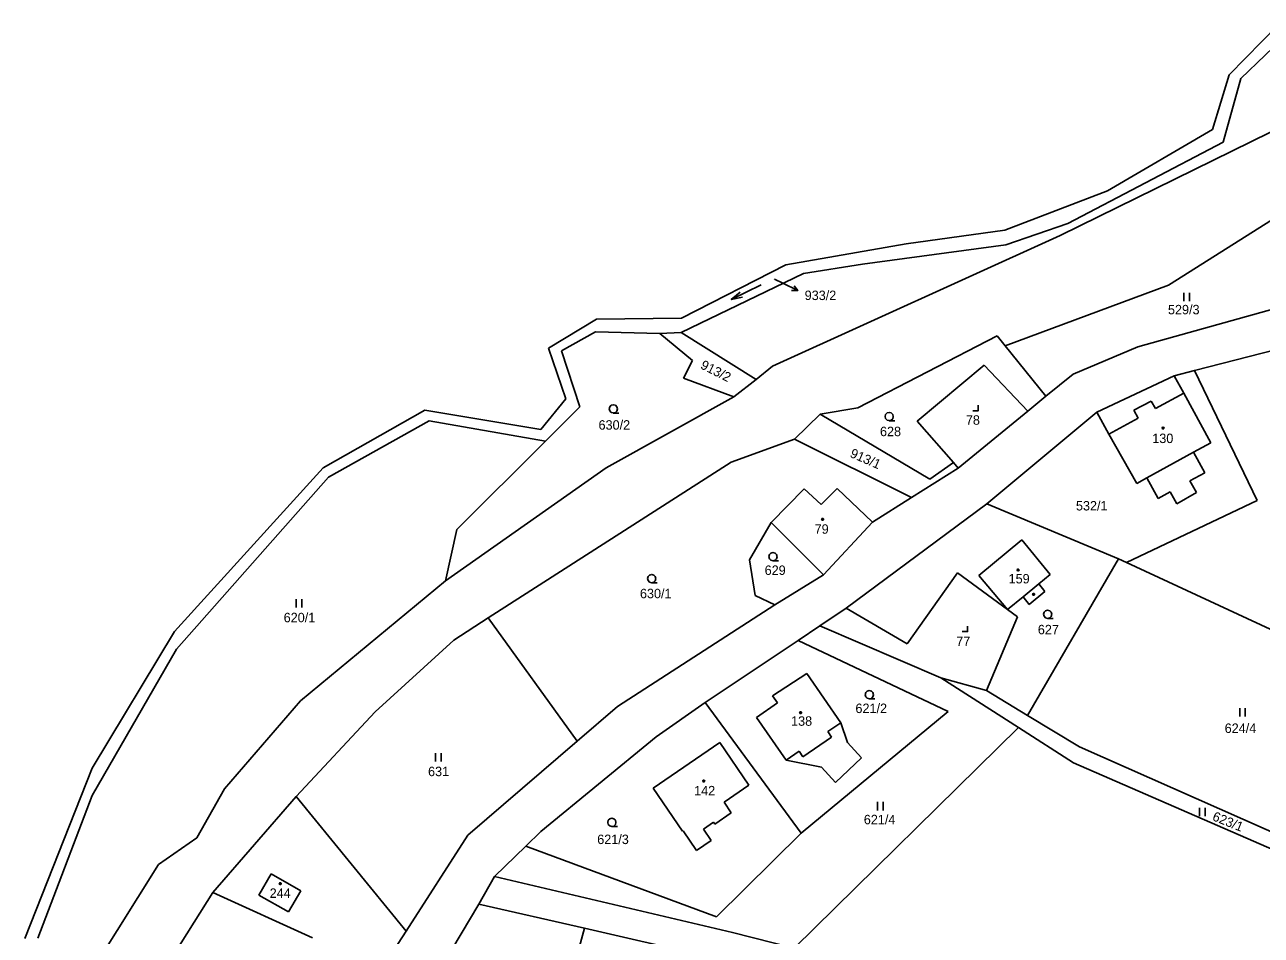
# Model space of a CAD drawing. Extents: x -580551 to -575069, y -1073031 to -1067931.
# Drawn here: x -578306.8 to -578084.3, y -1070524.1 to -1070360.2 of the extents above; entities that cross this region are included whole.
import ezdxf

# ---------------------------------------------------------------- set-up
doc = ezdxf.new("R2010")
doc.units = 0
for name, color, linetype in [('Druh pozemku', 7, 'Continuous'), ('Katastrální hranice', 7, 'Continuous'), ('Parcela', 7, 'Continuous'), ('Parcelní číslo', 7, 'Continuous'), ('Parcelní číslo_stavba', 7, 'Continuous'), ('Pomocná vrstva', 7, 'Continuous'), ('SR - hranice státu', 7, 'Continuous'), ('Vnitřní kresba', 7, 'Continuous')]:
    doc.layers.add(name, color=color, linetype=linetype)

msp = doc.modelspace()

# ---------------------------------------------------------------- linework, layer by layer
at = {"layer": 'Druh pozemku'}
for p, q in [((-578174.272, -1070407.069), (-578179.668, -1070409.691)), ((-578098.19, -1070408.5), (-578098.19, -1070410)), ((-578097.19, -1070410), (-578097.19, -1070408.5)), ((-578257.97, -1070463.65), (-578257.97, -1070465.15)), ((-578256.97, -1070465.15), (-578256.97, -1070463.65)), ((-578088.15, -1070483.24), (-578088.15, -1070484.74)), ((-578087.15, -1070484.74), (-578087.15, -1070483.24)), ((-578232.9, -1070491.36), (-578232.9, -1070492.86)), ((-578231.9, -1070492.86), (-578231.9, -1070491.36)), ((-578153.33, -1070500.13), (-578153.33, -1070501.63)), ((-578152.33, -1070501.63), (-578152.33, -1070500.13)), ((-578095.39, -1070501.16), (-578095.39, -1070502.66)), ((-578094.39, -1070502.66), (-578094.39, -1070501.16))]:
    msp.add_line(p, q, dxfattribs=at)
for points in [[(-578177.651, -1070409.267), (-578179.668, -1070409.691), (-578178.088, -1070408.367)], [(-578200.89, -1070430.11), (-578201.27, -1070430.01), (-578201.54, -1070429.74), (-578201.64, -1070429.37), (-578201.54, -1070429), (-578201.27, -1070428.73), (-578200.9, -1070428.63), (-578200.53, -1070428.73), (-578200.26, -1070429), (-578200.16, -1070429.38), (-578200.26, -1070429.76), (-578200.53, -1070430.03), (-578200.91, -1070430.13), (-578199.91, -1070430.13)], [(-578151.24, -1070431.49), (-578151.62, -1070431.39), (-578151.89, -1070431.12), (-578151.99, -1070430.75), (-578151.89, -1070430.38), (-578151.62, -1070430.11), (-578151.25, -1070430.01), (-578150.88, -1070430.11), (-578150.61, -1070430.38), (-578150.51, -1070430.76), (-578150.61, -1070431.14), (-578150.88, -1070431.41), (-578151.26, -1070431.51), (-578150.26, -1070431.51)], [(-578136.21, -1070429.7), (-578135.21, -1070429.7), (-578135.21, -1070428.7)], [(-578172.16, -1070456.71), (-578172.54, -1070456.61), (-578172.81, -1070456.34), (-578172.91, -1070455.97), (-578172.81, -1070455.6), (-578172.54, -1070455.33), (-578172.17, -1070455.23), (-578171.8, -1070455.33), (-578171.53, -1070455.6), (-578171.43, -1070455.98), (-578171.53, -1070456.36), (-578171.8, -1070456.63), (-578172.18, -1070456.73), (-578171.18, -1070456.73)], [(-578193.99, -1070460.66), (-578194.37, -1070460.56), (-578194.64, -1070460.29), (-578194.74, -1070459.92), (-578194.64, -1070459.55), (-578194.37, -1070459.28), (-578194, -1070459.18), (-578193.63, -1070459.28), (-578193.36, -1070459.55), (-578193.26, -1070459.93), (-578193.36, -1070460.31), (-578193.63, -1070460.58), (-578194.01, -1070460.68), (-578193.01, -1070460.68)], [(-578122.72, -1070467.08), (-578123.1, -1070466.98), (-578123.37, -1070466.71), (-578123.47, -1070466.34), (-578123.37, -1070465.97), (-578123.1, -1070465.7), (-578122.73, -1070465.6), (-578122.36, -1070465.7), (-578122.09, -1070465.97), (-578121.99, -1070466.35), (-578122.09, -1070466.73), (-578122.36, -1070467), (-578122.74, -1070467.1), (-578121.74, -1070467.1)], [(-578138.14, -1070469.46), (-578137.14, -1070469.46), (-578137.14, -1070468.46)], [(-578154.82, -1070481.56), (-578155.2, -1070481.46), (-578155.47, -1070481.19), (-578155.57, -1070480.82), (-578155.47, -1070480.45), (-578155.2, -1070480.18), (-578154.83, -1070480.08), (-578154.46, -1070480.18), (-578154.19, -1070480.45), (-578154.09, -1070480.83), (-578154.19, -1070481.21), (-578154.46, -1070481.48), (-578154.84, -1070481.58), (-578153.84, -1070481.58)], [(-578201.16, -1070504.53), (-578201.54, -1070504.43), (-578201.81, -1070504.16), (-578201.91, -1070503.79), (-578201.81, -1070503.42), (-578201.54, -1070503.15), (-578201.17, -1070503.05), (-578200.8, -1070503.15), (-578200.53, -1070503.42), (-578200.43, -1070503.8), (-578200.53, -1070504.18), (-578200.8, -1070504.45), (-578201.18, -1070504.55), (-578200.18, -1070504.55)]]:
    msp.add_lwpolyline(points, dxfattribs=at)
for points in [[(-578101.87, -1070432.67), (-578101.78, -1070432.82), (-578101.87, -1070432.97), (-578102.05, -1070432.97), (-578102.14, -1070432.82), (-578102.05, -1070432.67)], [(-578163.16, -1070449.08), (-578163.07, -1070449.23), (-578163.16, -1070449.38), (-578163.34, -1070449.38), (-578163.43, -1070449.23), (-578163.34, -1070449.08)], [(-578127.97, -1070458.21), (-578127.88, -1070458.36), (-578127.97, -1070458.51), (-578128.15, -1070458.51), (-578128.24, -1070458.36), (-578128.15, -1070458.21)], [(-578125.18, -1070462.63), (-578125.09, -1070462.78), (-578125.18, -1070462.93), (-578125.36, -1070462.93), (-578125.45, -1070462.78), (-578125.36, -1070462.63)], [(-578167.1, -1070483.91), (-578167.01, -1070484.06), (-578167.1, -1070484.21), (-578167.28, -1070484.21), (-578167.37, -1070484.06), (-578167.28, -1070483.91)], [(-578184.53, -1070496.23), (-578184.44, -1070496.38), (-578184.53, -1070496.53), (-578184.71, -1070496.53), (-578184.8, -1070496.38), (-578184.71, -1070496.23)], [(-578260.76, -1070514.67), (-578260.67, -1070514.82), (-578260.76, -1070514.97), (-578260.94, -1070514.97), (-578261.03, -1070514.82), (-578260.94, -1070514.67)]]:
    msp.add_lwpolyline(points, close=True, dxfattribs=at)
at = {"layer": 'Katastrální hranice'}
for p, q in [((-578090.07, -1070369.27), (-578081.21, -1070360.24)), ((-578093.08, -1070379.09), (-578090.07, -1070369.27)), ((-578111.94, -1070390.14), (-578093.08, -1070379.09)), ((-578130.45, -1070397.24), (-578111.94, -1070390.14)), ((-578148.17, -1070399.69), (-578130.45, -1070397.24)), ((-578169.88, -1070403.44), (-578148.17, -1070399.69)), ((-578188.61, -1070413.04), (-578169.88, -1070403.44)), ((-578212.57, -1070418.48), (-578203.92, -1070413.25)), ((-578203.92, -1070413.25), (-578188.61, -1070413.04)), ((-578209.48, -1070427.59), (-578212.57, -1070418.48)), ((-578213.98, -1070433.07), (-578209.48, -1070427.59)), ((-578253.13, -1070439.99), (-578234.84, -1070429.62)), ((-578234.84, -1070429.62), (-578213.98, -1070433.07)), ((-578279.91, -1070469.44), (-578253.13, -1070439.99)), ((-578294.73, -1070494.02), (-578279.91, -1070469.44)), ((-578306.85, -1070524.72), (-578294.73, -1070494.02))]:
    msp.add_line(p, q, dxfattribs=at)
at = {"layer": 'Parcela'}
for p, q in [((-578079.06, -1070361.34), (-578087.95, -1070369.9)), ((-578087.95, -1070369.9), (-578091.11, -1070381.36)), ((-578064.77, -1070370.78), (-578120.48, -1070398.15)), ((-578091.11, -1070381.36), (-578119.12, -1070396.04)), ((-578119.12, -1070396.04), (-578130.25, -1070399.86)), ((-578081.13, -1070394.58), (-578100.99, -1070407.13)), ((-578120.48, -1070398.15), (-578172.26, -1070421.72)), ((-578130.25, -1070399.86), (-578156.04, -1070403.34)), ((-578156.04, -1070403.34), (-578166.65, -1070405.03)), ((-578166.65, -1070405.03), (-578188.72, -1070415.66)), ((-578100.99, -1070407.13), (-578130.38, -1070418.04)), ((-578070.24, -1070408.05), (-578106.52, -1070418.22)), ((-578096.29, -1070422.48), (-578057.57, -1070412.49)), ((-578204.09, -1070415.5), (-578210.21, -1070418.95)), ((-578192.56, -1070415.79), (-578204.09, -1070415.5)), ((-578192.56, -1070415.79), (-578188.72, -1070415.66)), ((-578186.67, -1070420.67), (-578192.56, -1070415.79)), ((-578188.72, -1070415.66), (-578175.21, -1070424.06)), ((-578156.89, -1070429.17), (-578131.84, -1070416.25)), ((-578131.84, -1070416.25), (-578130.38, -1070418.04)), ((-578210.21, -1070418.95), (-578206.96, -1070429.01)), ((-578130.38, -1070418.04), (-578123.03, -1070427.11)), ((-578106.52, -1070418.22), (-578118.13, -1070423.14)), ((-578188.26, -1070423.87), (-578186.67, -1070420.67)), ((-578172.26, -1070421.72), (-578175.21, -1070424.06)), ((-578146.24, -1070431.56), (-578134.15, -1070421.49)), ((-578134.15, -1070421.49), (-578126.29, -1070429.78)), ((-578118.13, -1070423.14), (-578123.03, -1070427.11)), ((-578113.88, -1070429.97), (-578099.95, -1070423.42)), ((-578099.95, -1070423.42), (-578096.29, -1070422.48)), ((-578098.23, -1070426.55), (-578099.95, -1070423.42)), ((-578085, -1070445.89), (-578096.29, -1070422.48)), ((-578179.24, -1070427.22), (-578188.26, -1070423.87)), ((-578175.21, -1070424.06), (-578179.24, -1070427.22)), ((-578179.24, -1070427.22), (-578202.19, -1070440.01)), ((-578123.03, -1070427.11), (-578126.29, -1070429.78)), ((-578093.37, -1070435.46), (-578098.23, -1070426.55)), ((-578206.96, -1070429.01), (-578213.14, -1070435.18)), ((-578163.7, -1070430.31), (-578156.89, -1070429.17)), ((-578126.29, -1070429.78), (-578138.83, -1070440.05)), ((-578133.65, -1070446.48), (-578113.88, -1070429.97)), ((-578113.88, -1070429.97), (-578111.71, -1070433.93)), ((-578234.08, -1070431.54), (-578252.17, -1070441.68)), ((-578213.14, -1070435.18), (-578234.08, -1070431.54)), ((-578168.3, -1070434.83), (-578163.7, -1070430.31)), ((-578163.7, -1070430.31), (-578143.95, -1070442.04)), ((-578139.7, -1070439.05), (-578146.24, -1070431.56)), ((-578111.71, -1070433.93), (-578106.69, -1070442.8)), ((-578213.14, -1070435.18), (-578229.1, -1070451.09)), ((-578179.67, -1070438.98), (-578168.3, -1070434.83)), ((-578168.3, -1070434.83), (-578147.22, -1070445.31)), ((-578096.48, -1070437.17), (-578093.37, -1070435.46)), ((-578223.42, -1070467), (-578179.67, -1070438.98)), ((-578094.45, -1070440.87), (-578096.48, -1070437.17)), ((-578202.19, -1070440.01), (-578231.11, -1070460.35)), ((-578138.83, -1070440.05), (-578147.22, -1070445.31)), ((-578143.95, -1070442.04), (-578139.7, -1070439.05)), ((-578138.83, -1070440.05), (-578139.7, -1070439.05)), ((-578097.13, -1070442.35), (-578094.45, -1070440.87)), ((-578252.17, -1070441.68), (-578279.52, -1070472.61)), ((-578106.69, -1070442.8), (-578104.9, -1070441.81)), ((-578104.9, -1070441.81), (-578102.84, -1070445.53)), ((-578095.95, -1070444.45), (-578097.13, -1070442.35)), ((-578172.51, -1070449.8), (-578166.57, -1070443.79)), ((-578166.57, -1070443.79), (-578163.48, -1070446.59)), ((-578163.48, -1070446.59), (-578160.64, -1070443.72)), ((-578160.64, -1070443.72), (-578154.25, -1070449.77)), ((-578147.22, -1070445.31), (-578154.25, -1070449.77)), ((-578102.84, -1070445.53), (-578100.67, -1070444.32)), ((-578100.67, -1070444.32), (-578099.47, -1070446.44)), ((-578099.47, -1070446.44), (-578095.95, -1070444.45)), ((-578133.65, -1070446.48), (-578158.97, -1070465.24)), ((-578109.99, -1070456.34), (-578133.65, -1070446.48)), ((-578108.53, -1070457.02), (-578085, -1070445.89)), ((-578176.41, -1070456.57), (-578172.51, -1070449.8)), ((-578172.51, -1070449.8), (-578163.09, -1070459.25)), ((-578154.25, -1070449.77), (-578163.09, -1070459.25)), ((-578229.1, -1070451.09), (-578231.11, -1070460.35)), ((-578135.11, -1070459.34), (-578127.39, -1070452.93)), ((-578127.39, -1070452.93), (-578122.26, -1070459.19)), ((-578175.4, -1070462.99), (-578176.41, -1070456.57)), ((-578109.99, -1070456.34), (-578126.34, -1070484.57)), ((-578108.53, -1070457.02), (-578109.99, -1070456.34)), ((-578148.02, -1070471.69), (-578138.93, -1070458.91)), ((-578138.93, -1070458.91), (-578129.95, -1070465.49)), ((-578081, -1070469.8), (-578108.53, -1070457.02)), ((-578231.11, -1070460.35), (-578257.23, -1070481.93)), ((-578163.09, -1070459.25), (-578171.83, -1070464.67)), ((-578129.95, -1070465.49), (-578135.11, -1070459.34)), ((-578122.26, -1070459.19), (-578124.33, -1070460.89)), ((-578124.33, -1070460.89), (-578123.22, -1070462.24)), ((-578171.83, -1070464.67), (-578175.4, -1070462.99)), ((-578127.16, -1070463.2), (-578129.95, -1070465.49)), ((-578126.05, -1070464.56), (-578127.16, -1070463.2)), ((-578123.22, -1070462.24), (-578126.05, -1070464.56)), ((-578171.83, -1070464.67), (-578200.17, -1070482.94)), ((-578158.97, -1070465.24), (-578163.71, -1070468.41)), ((-578158.97, -1070465.24), (-578148.02, -1070471.69)), ((-578129.95, -1070465.49), (-578128.17, -1070466.8)), ((-578229.64, -1070470.98), (-578223.42, -1070467)), ((-578223.42, -1070467), (-578207.4, -1070489.17)), ((-578128.17, -1070466.8), (-578133.75, -1070480.08)), ((-578163.71, -1070468.41), (-578167.65, -1070471.05)), ((-578141.97, -1070477.81), (-578163.71, -1070468.41)), ((-578243.76, -1070483.88), (-578229.64, -1070470.98)), ((-578167.65, -1070471.05), (-578184.4, -1070482.24)), ((-578167.65, -1070471.05), (-578140.62, -1070483.87)), ((-578279.52, -1070472.61), (-578294.71, -1070498.96)), ((-578172.27, -1070481.01), (-578166.08, -1070477.02)), ((-578166.08, -1070477.02), (-578159.95, -1070485.87)), ((-578133.75, -1070480.08), (-578141.97, -1070477.81)), ((-578127.99, -1070486.75), (-578141.97, -1070477.81)), ((-578171.36, -1070482.29), (-578172.27, -1070481.01)), ((-578126.34, -1070484.57), (-578133.75, -1070480.08)), ((-578257.23, -1070481.93), (-578270.9, -1070497.78)), ((-578200.17, -1070482.94), (-578207.4, -1070489.17)), ((-578184.4, -1070482.24), (-578193.19, -1070488.39)), ((-578184.4, -1070482.24), (-578167.11, -1070505.74)), ((-578175.15, -1070484.9), (-578171.36, -1070482.29)), ((-578257.99, -1070499.14), (-578243.76, -1070483.88)), ((-578169.82, -1070492.58), (-578175.15, -1070484.9)), ((-578140.62, -1070483.87), (-578167.11, -1070505.74)), ((-578117.01, -1070490.23), (-578126.34, -1070484.57)), ((-578168.38, -1070526.44), (-578127.99, -1070486.75)), ((-578158.76, -1070489.45), (-578159.95, -1070485.87)), ((-578118.06, -1070493.1), (-578127.99, -1070486.75)), ((-578207.4, -1070489.17), (-578227.07, -1070506.12)), ((-578193.19, -1070488.39), (-578213.98, -1070505.45)), ((-578181.75, -1070489.45), (-578193.72, -1070497.66)), ((-578176.51, -1070497.11), (-578181.75, -1070489.45)), ((-578156.22, -1070492.17), (-578158.76, -1070489.45)), ((-578160.89, -1070496.65), (-578156.22, -1070492.17)), ((-578067.62, -1070512.04), (-578117.01, -1070490.23)), ((-578169.82, -1070492.58), (-578163.41, -1070493.86)), ((-578163.41, -1070493.86), (-578160.89, -1070496.65)), ((-578059.03, -1070518.81), (-578118.06, -1070493.1)), ((-578294.71, -1070498.96), (-578304.49, -1070524.64)), ((-578270.9, -1070497.78), (-578275.88, -1070506.6)), ((-578193.72, -1070497.66), (-578188.43, -1070505.37)), ((-578180.97, -1070500.16), (-578176.51, -1070497.11)), ((-578272.99, -1070516.43), (-578257.99, -1070499.14)), ((-578257.99, -1070499.14), (-578238.22, -1070523.39)), ((-578179.67, -1070502.06), (-578180.97, -1070500.16)), ((-578182.65, -1070504.09), (-578179.67, -1070502.06)), ((-578213.98, -1070505.45), (-578216.67, -1070508.06)), ((-578188.43, -1070505.37), (-578188.35, -1070505.31)), ((-578188.35, -1070505.31), (-578185.92, -1070508.87)), ((-578184.69, -1070505), (-578182.87, -1070503.75)), ((-578183.28, -1070507.06), (-578184.69, -1070505)), ((-578182.87, -1070503.75), (-578182.65, -1070504.09)), ((-578167.11, -1070505.74), (-578182.36, -1070520.79)), ((-578275.88, -1070506.6), (-578282.8, -1070511.36)), ((-578227.07, -1070506.12), (-578238.22, -1070523.39)), ((-578185.92, -1070508.87), (-578183.28, -1070507.06)), ((-578216.67, -1070508.06), (-578222.3, -1070513.55)), ((-578216.67, -1070508.06), (-578182.36, -1070520.79)), ((-578282.8, -1070511.36), (-578304.04, -1070545.35)), ((-578264.73, -1070516.87), (-578262.5, -1070513.03)), ((-578262.5, -1070513.03), (-578257.18, -1070516.12)), ((-578222.3, -1070513.55), (-578225.1, -1070518.49)), ((-578179.44, -1070523.64), (-578222.3, -1070513.55)), ((-578284.43, -1070534.61), (-578272.99, -1070516.43)), ((-578259.4, -1070519.92), (-578264.73, -1070516.87)), ((-578257.18, -1070516.12), (-578259.4, -1070519.92)), ((-578225.1, -1070518.49), (-578240.19, -1070543.87)), ((-578225.1, -1070518.49), (-578206.11, -1070522.84)), ((-578238.22, -1070523.39), (-578242.66, -1070530.27)), ((-578206.11, -1070522.84), (-578211.9, -1070543.82)), ((-578206.11, -1070522.84), (-578195.97, -1070525.17)), ((-578168.38, -1070526.44), (-578179.44, -1070523.64))]:
    msp.add_line(p, q, dxfattribs=at)
at = {"layer": 'Pomocná vrstva'}
for p in [(-578171.88, -1070406.04), (-578167.697, -1070408.092)]:
    msp.add_line(p, (-578170.39, -1070406.77), dxfattribs=at)
msp.add_lwpolyline([(-578168.374, -1070407.203), (-578167.697, -1070408.092), (-578168.815, -1070408.1)], dxfattribs=at)
at = {"layer": 'SR - hranice státu'}
for points in [[(-578127.99, -1070486.75), (-578141.97, -1070477.81), (-578133.75, -1070480.08), (-578126.34, -1070484.57), (-578109.99, -1070456.34)], [(-578109.99, -1070456.34), (-578108.53, -1070457.02), (-578081, -1070469.8), (-578053.52, -1070482.42), (-578040.28, -1070488.5)], [(-578185.13, -1070527.66), (-578195.97, -1070525.17), (-578206.11, -1070522.84), (-578225.1, -1070518.49), (-578222.3, -1070513.55), (-578179.44, -1070523.64), (-578168.38, -1070526.44), (-578127.99, -1070486.75)]]:
    msp.add_lwpolyline(points, dxfattribs=at)
at = {"layer": 'Vnitřní kresba'}
for p, q in [((-578098.23, -1070426.55), (-578103.3, -1070429.33)), ((-578107.21, -1070429.63), (-578104.1, -1070427.99)), ((-578106.46, -1070431.06), (-578107.21, -1070429.63)), ((-578104.1, -1070427.99), (-578103.3, -1070429.33)), ((-578106.46, -1070431.06), (-578111.71, -1070433.93)), ((-578104.9, -1070441.81), (-578096.48, -1070437.17)), ((-578124.33, -1070460.89), (-578127.16, -1070463.2)), ((-578159.95, -1070485.87), (-578162.29, -1070487.46)), ((-578162.29, -1070487.46), (-578161.61, -1070488.47)), ((-578161.61, -1070488.47), (-578166.8, -1070491.99)), ((-578167.48, -1070490.99), (-578169.82, -1070492.58)), ((-578166.8, -1070491.99), (-578167.48, -1070490.99)), ((-578272.99, -1070516.43), (-578255.06, -1070524.59))]:
    msp.add_line(p, q, dxfattribs=at)

# ---------------------------------------------------------------- texts
at = {"layer": 'Parcelní číslo'}
for s, height, p in [('933/2', 0.1, (-578172.097, -1070406.04)), ('529/3', 1.7, (-578101.072, -1070412.36)), ('630/2', 1.7, (-578203.565, -1070433.12)), ('628', 1.7, (-578152.907, -1070434.29)), ('532/1', 1.7, (-578117.635, -1070447.66)), ('629', 1.7, (-578173.669, -1070459.26)), ('630/1', 1.7, (-578196.113, -1070463.46)), ('620/1', 1.7, (-578260.241, -1070467.78)), ('627', 1.7, (-578124.494, -1070469.95)), ('621/2', 1.7, (-578157.322, -1070484.12)), ('624/4', 1.7, (-578090.864, -1070487.7)), ('631', 1.7, (-578234.254, -1070495.48)), ('621/4', 1.7, (-578155.817, -1070504.14)), ('621/3', 1.7, (-578203.804, -1070507.7))]:
    msp.add_text(s, height=height, dxfattribs=at).set_placement(p)
for s, rotation, p in [('913/2', 333.06037, (-578185.363, -1070422.022)), ('913/1', 336.44082, (-578158.444, -1070437.984)), ('623/1', 337.93051, (-578093.214, -1070503.364))]:
    msp.add_text(s, height=1.7, rotation=rotation, dxfattribs=at).set_placement(p)
at = {"layer": 'Parcelní číslo_stavba'}
for s, p in [('78', (-578137.448, -1070432.23)), ('130', (-578103.898, -1070435.53)), ('79', (-578164.671, -1070451.85)), ('159', (-578129.759, -1070460.79)), ('77', (-578139.185, -1070472.07)), ('138', (-578168.912, -1070486.41)), ('142', (-578186.362, -1070498.94)), ('244', (-578262.759, -1070517.38))]:
    msp.add_text(s, height=1.7, dxfattribs=at).set_placement(p)
at = {"layer": 'Pomocná vrstva'}
msp.add_text('933/2', height=1.7, dxfattribs=at).set_placement((-578166.463, -1070409.79))

doc.saveas('drawing.dxf')
